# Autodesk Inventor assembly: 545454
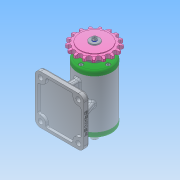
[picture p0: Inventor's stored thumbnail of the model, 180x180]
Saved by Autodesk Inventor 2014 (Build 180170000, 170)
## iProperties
Created: 2019-06
Part Number: 545454
Document SubType Name: Assembly
Designer: NET
Author: NET
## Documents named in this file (11)
- C:\Users\NET\Desktop\545454.iam
- C:\Users\NET\Desktop\787878.ipt
- C:\Users\NET\Desktop\축.ipt
- C:\Users\NET\Desktop\베어링 6203.ipt
- C:\Users\NET\Desktop\커버.ipt
- C:\Users\NET\Desktop\키 4x4x12.ipt
- C:\Users\NET\Desktop\스프로킷.ipt
- C:\Users\NET\Desktop\평와셔.ipt
- C:\Users\NET\Desktop\스프링와셔.ipt
- C:\Users\NET\Desktop\볼트 M4.ipt
- C:\Users\NET\Desktop\오일 실 17 30 5.ipt
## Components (1 placed, 1 different names)
1. 787878:1
